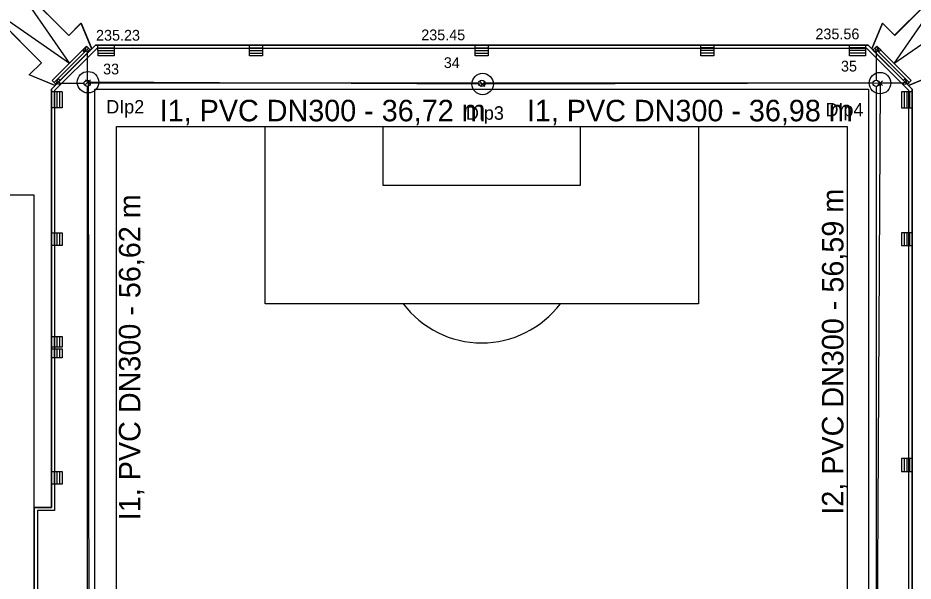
# Model space of a CAD drawing. Extents: x -264234 to -263604, y -1242346 to -1242049.
# Drawn here: x -263895.1 to -263811.8, y -1242154.2 to -1242101.8 of the extents above; entities that cross this region are included whole.
import ezdxf

# ---------------------------------------------------------------- set-up
doc = ezdxf.new("R2010")
doc.units = 0
for name, color, linetype in [('KFA_BODY_CISLO', 7, 'Continuous'), ('KFA_BODY_SYMBOL', 7, 'Continuous'), ('KFA_BODY_VYSKA', 7, 'Continuous'), ('KFA_DAZDOVA_KANALIZACIA_vetva_I', 7, 'Continuous'), ('KFA_DAZDOVA_KANALIZACIA_vetva_I_popis', 7, 'Continuous'), ('KFA_SITUACIA_DSP', 7, 'Continuous')]:
    doc.layers.add(name, color=color, linetype=linetype)

msp = doc.modelspace()

# ---------------------------------------------------------------- linework, layer by layer
at = {"layer": 'KFA_BODY_SYMBOL'}
for p, q in [((-263888.827, -1242107.994), (-263888.385, -1242107.552)), ((-263888.385, -1242107.994), (-263888.827, -1242107.552)), ((-263852.108, -1242108.166), (-263851.666, -1242107.724)), ((-263851.666, -1242108.166), (-263852.108, -1242107.724)), ((-263815.128, -1242108.077), (-263814.686, -1242107.635)), ((-263814.686, -1242108.077), (-263815.128, -1242107.635))]:
    msp.add_line(p, q, dxfattribs=at)
at = {"layer": 'KFA_DAZDOVA_KANALIZACIA_vetva_I'}
for points in [[(-263814.907, -1242107.856), (-263815.198, -1242164.443), (-263815.189, -1242220.791), (-263852.152, -1242220.736), (-263888.701, -1242220.786), (-263906.731, -1242239.259)], [(-263814.907, -1242107.856), (-263851.887, -1242107.945), (-263888.606, -1242107.773), (-263888.523, -1242164.395), (-263888.701, -1242220.786)]]:
    msp.add_lwpolyline(points, dxfattribs=at)
for centre in [(-263888.606, -1242107.773), (-263851.887, -1242107.945), (-263814.907, -1242107.856)]:
    msp.add_circle(centre, 1, dxfattribs=at)
at = {"layer": 'KFA_SITUACIA_DSP'}
for p, q in [((-263891.932, -1242107.613), (-263888.75, -1242104.431)), ((-263891.749, -1242107.795), (-263888.567, -1242104.614)), ((-263888.75, -1242104.431), (-263889.103, -1242104.785)), ((-263888.921, -1242104.967), (-263888.75, -1242104.431)), ((-263888.918, -1242104.964), (-263888.75, -1242104.431)), ((-263888.566, -1242104.615), (-263888.75, -1242104.431)), ((-263888.383, -1242104.797), (-263888.567, -1242104.614)), ((-263887.677, -1242105.332), (-263887.678, -1242104.353)), ((-263887.677, -1242104.582), (-263886.179, -1242104.582)), ((-263886.179, -1242104.332), (-263886.179, -1242105.332)), ((-263873.567, -1242105.332), (-263873.571, -1242104.345)), ((-263873.567, -1242104.582), (-263872.369, -1242104.582)), ((-263872.369, -1242104.332), (-263872.369, -1242105.332)), ((-263852.567, -1242105.332), (-263852.567, -1242104.332)), ((-263852.567, -1242104.582), (-263851.369, -1242104.582)), ((-263851.369, -1242104.332), (-263851.369, -1242105.332)), ((-263831.567, -1242105.332), (-263831.567, -1242104.332)), ((-263830.369, -1242104.582), (-263831.567, -1242104.582)), ((-263830.369, -1242104.332), (-263830.369, -1242105.332)), ((-263817.757, -1242105.332), (-263817.757, -1242104.332)), ((-263816.259, -1242104.582), (-263817.757, -1242104.582)), ((-263816.259, -1242104.332), (-263816.259, -1242105.332)), ((-263815.567, -1242104.787), (-263815.383, -1242104.604)), ((-263815.385, -1242104.605), (-263815.201, -1242104.421)), ((-263812.202, -1242107.786), (-263815.383, -1242104.604)), ((-263812.019, -1242107.603), (-263815.201, -1242104.421)), ((-263815.03, -1242104.957), (-263815.201, -1242104.421)), ((-263815.031, -1242104.959), (-263814.847, -1242104.775)), ((-263888.383, -1242104.797), (-263891.565, -1242107.979)), ((-263888.919, -1242104.969), (-263889.103, -1242104.785)), ((-263889.103, -1242104.785), (-263888.921, -1242104.967)), ((-263888.921, -1242104.967), (-263888.918, -1242104.964)), ((-263888.673, -1242104.962), (-263888.673, -1242107.577)), ((-263887.677, -1242104.832), (-263886.179, -1242104.832)), ((-263887.677, -1242105.082), (-263886.179, -1242105.082)), ((-263886.179, -1242105.332), (-263887.677, -1242105.332)), ((-263873.567, -1242104.832), (-263872.369, -1242104.832)), ((-263873.567, -1242105.082), (-263872.369, -1242105.082)), ((-263872.369, -1242105.332), (-263873.567, -1242105.332)), ((-263852.567, -1242104.832), (-263851.369, -1242104.832)), ((-263852.567, -1242105.082), (-263851.369, -1242105.082)), ((-263851.369, -1242105.332), (-263852.567, -1242105.332)), ((-263830.369, -1242104.832), (-263831.567, -1242104.832)), ((-263830.369, -1242105.082), (-263831.567, -1242105.082)), ((-263830.369, -1242105.332), (-263831.567, -1242105.332)), ((-263816.259, -1242104.832), (-263817.757, -1242104.832)), ((-263816.259, -1242105.082), (-263817.757, -1242105.082)), ((-263816.259, -1242105.332), (-263817.757, -1242105.332)), ((-263815.567, -1242104.787), (-263812.385, -1242107.97)), ((-263815.263, -1242104.962), (-263815.263, -1242107.577)), ((-263891.748, -1242107.797), (-263891.932, -1242107.613)), ((-263891.396, -1242107.442), (-263891.749, -1242107.795)), ((-263891.565, -1242107.979), (-263891.749, -1242107.795)), ((-263891.749, -1242107.795), (-263891.565, -1242107.979)), ((-263891.517, -1242107.934), (-263891.673, -1242108.089)), ((-263891.565, -1242107.979), (-263891.396, -1242107.442)), ((-263891.565, -1242107.979), (-263891.396, -1242107.442)), ((-263891.212, -1242107.626), (-263891.396, -1242107.442)), ((-263891.218, -1242107.877), (-263888.973, -1242107.877)), ((-263852.268, -1242107.877), (-263888.373, -1242107.877)), ((-263815.563, -1242107.877), (-263851.668, -1242107.877)), ((-263812.717, -1242107.877), (-263814.963, -1242107.877)), ((-263812.739, -1242107.616), (-263812.555, -1242107.432)), ((-263812.385, -1242107.97), (-263812.555, -1242107.432)), ((-263812.385, -1242107.97), (-263812.202, -1242107.786)), ((-263812.203, -1242107.787), (-263812.019, -1242107.603)), ((-263891.018, -1242108.673), (-263892.012, -1242108.664)), ((-263891.768, -1242108.673), (-263891.768, -1242110.171)), ((-263891.518, -1242108.673), (-263891.518, -1242110.171)), ((-263891.268, -1242108.673), (-263891.268, -1242110.171)), ((-263891.018, -1242108.673), (-263891.018, -1242110.171)), ((-263888.673, -1242108.177), (-263888.673, -1242164.087)), ((-263815.263, -1242108.177), (-263815.263, -1242164.087)), ((-263811.918, -1242108.673), (-263812.918, -1242108.673)), ((-263812.918, -1242108.673), (-263812.918, -1242110.172)), ((-263812.668, -1242108.673), (-263812.668, -1242110.172)), ((-263812.418, -1242108.673), (-263812.418, -1242110.172)), ((-263812.168, -1242108.673), (-263812.168, -1242110.172)), ((-263891.018, -1242110.171), (-263891.997, -1242110.171)), ((-263812.918, -1242110.172), (-263811.918, -1242110.172)), ((-263892.018, -1242121.782), (-263891.018, -1242121.782)), ((-263891.768, -1242121.782), (-263891.768, -1242122.982)), ((-263891.518, -1242121.782), (-263891.518, -1242122.982)), ((-263891.268, -1242121.782), (-263891.268, -1242122.982)), ((-263891.018, -1242121.782), (-263891.018, -1242122.982)), ((-263811.918, -1242121.782), (-263812.918, -1242121.782)), ((-263812.918, -1242121.782), (-263812.918, -1242122.982)), ((-263812.668, -1242121.782), (-263812.668, -1242122.982)), ((-263812.418, -1242121.782), (-263812.418, -1242122.982)), ((-263812.168, -1242121.782), (-263812.168, -1242122.982)), ((-263891.018, -1242122.982), (-263892.018, -1242122.982)), ((-263812.918, -1242122.982), (-263811.918, -1242122.982)), ((-263891.997, -1242131.433), (-263891.018, -1242131.433)), ((-263891.768, -1242131.433), (-263891.768, -1242132.431)), ((-263891.518, -1242131.433), (-263891.518, -1242132.431)), ((-263891.268, -1242131.433), (-263891.268, -1242132.431)), ((-263891.018, -1242131.433), (-263891.018, -1242132.431)), ((-263891.018, -1242132.431), (-263892.018, -1242132.431)), ((-263892.018, -1242132.583), (-263891.018, -1242132.583)), ((-263891.768, -1242132.583), (-263891.768, -1242133.431)), ((-263891.518, -1242132.583), (-263891.518, -1242133.431)), ((-263891.268, -1242132.583), (-263891.268, -1242133.431)), ((-263891.018, -1242132.583), (-263891.018, -1242133.431)), ((-263891.018, -1242133.431), (-263892.018, -1242133.431)), ((-263811.918, -1242142.782), (-263812.918, -1242142.782)), ((-263812.918, -1242142.782), (-263812.918, -1242143.982)), ((-263812.668, -1242142.782), (-263812.668, -1242143.982)), ((-263812.418, -1242142.782), (-263812.418, -1242143.982)), ((-263812.168, -1242142.782), (-263812.168, -1242143.982)), ((-263892.018, -1242143.983), (-263891.018, -1242143.983)), ((-263891.768, -1242143.983), (-263891.768, -1242145.181)), ((-263891.518, -1242143.983), (-263891.518, -1242145.181)), ((-263891.268, -1242143.983), (-263891.268, -1242145.181)), ((-263891.018, -1242143.983), (-263891.018, -1242145.181)), ((-263812.918, -1242143.982), (-263811.918, -1242143.982)), ((-263891.018, -1242145.181), (-263892.018, -1242145.181))]:
    msp.add_line(p, q, dxfattribs=at)
for points in [[(-263891.681, -1242108.095), (-263894.08, -1242107.101), (-263892.944, -1242105.964), (-263898.552, -1242100.364), (-263896.003, -1242097.814), (-263890.399, -1242103.418), (-263889.262, -1242102.282), (-263888.268, -1242104.681), (-263891.681, -1242108.095)], [(-263898.54, -1242100.355), (-263895.995, -1242097.81), (-263890.341, -1242106.025), (-263898.533, -1242100.366)], [(-263812.269, -1242108.085), (-263809.87, -1242107.09), (-263811.006, -1242105.954), (-263805.4, -1242100.352), (-263807.949, -1242097.803), (-263813.552, -1242103.408), (-263814.689, -1242102.272), (-263815.683, -1242104.672), (-263812.269, -1242108.085)], [(-263805.395, -1242100.355), (-263807.941, -1242097.809), (-263813.618, -1242106.02), (-263805.402, -1242100.365)], [(-263893.618, -1242181.432), (-263893.618, -1242147.332), (-263892.018, -1242147.332), (-263892.018, -1242108.434), (-263891.673, -1242108.09), (-263894.073, -1242107.096), (-263892.937, -1242105.959), (-263896.896, -1242101.999), (-263894.351, -1242099.454), (-263890.391, -1242103.413), (-263889.254, -1242102.277), (-263888.26, -1242104.677), (-263887.916, -1242104.332), (-263816.02, -1242104.332), (-263815.675, -1242104.677), (-263814.681, -1242102.277), (-263813.545, -1242103.413), (-263809.585, -1242099.454), (-263807.039, -1242101.999), (-263810.999, -1242105.959), (-263809.862, -1242107.096), (-263812.262, -1242108.09), (-263811.918, -1242108.434), (-263811.918, -1242220.33)]]:
    msp.add_lwpolyline(points, dxfattribs=at)
for points in [[(-263816.02, -1242224.432), (-263811.918, -1242220.33), (-263811.918, -1242108.434), (-263816.02, -1242104.332), (-263887.916, -1242104.332), (-263892.018, -1242108.434), (-263892.018, -1242147.332), (-263893.618, -1242147.332), (-263893.618, -1242162.382), (-263894.718, -1242162.382), (-263894.718, -1242166.382), (-263893.618, -1242166.382), (-263893.618, -1242181.432), (-263892.018, -1242181.432), (-263892.018, -1242220.33), (-263887.916, -1242224.432)], [(-263816.144, -1242224.132), (-263812.218, -1242220.206), (-263812.218, -1242108.558), (-263816.144, -1242104.632), (-263887.792, -1242104.632), (-263891.718, -1242108.558), (-263891.718, -1242147.632), (-263893.318, -1242147.632), (-263893.318, -1242162.682), (-263894.418, -1242162.682), (-263894.418, -1242166.082), (-263893.318, -1242166.082), (-263893.318, -1242181.132), (-263891.718, -1242181.132), (-263891.718, -1242220.206), (-263887.792, -1242224.132)], [(-263815.201, -1242104.421), (-263815.03, -1242104.957), (-263814.847, -1242104.775)], [(-263812.385, -1242107.97), (-263812.202, -1242107.786), (-263812.555, -1242107.432)], [(-263887.968, -1242108.434), (-263815.968, -1242108.434), (-263815.968, -1242220.33), (-263887.968, -1242220.33)], [(-263885.968, -1242111.882), (-263817.968, -1242111.882), (-263817.968, -1242216.882), (-263885.968, -1242216.882)], [(-263831.808, -1242128.382), (-263872.128, -1242128.382), (-263872.128, -1242111.882), (-263831.808, -1242111.882)], [(-263842.808, -1242117.382), (-263861.128, -1242117.382), (-263861.128, -1242111.882), (-263842.808, -1242111.882)], [(-263893.618, -1242118.282), (-263916.093, -1242118.282), (-263916.093, -1242175.482), (-263914.293, -1242175.482), (-263914.293, -1242210.482), (-263893.618, -1242210.482), (-263893.618, -1242166.382), (-263900.043, -1242166.382), (-263900.043, -1242162.382), (-263893.618, -1242162.382)]]:
    msp.add_lwpolyline(points, close=True, dxfattribs=at)
for centre, radius in [((-263888.673, -1242104.862), 0.1), ((-263815.263, -1242104.862), 0.1), ((-263891.318, -1242107.877), 0.1), ((-263888.673, -1242107.877), 0.3), ((-263851.968, -1242107.877), 0.3), ((-263815.263, -1242107.877), 0.3), ((-263812.617, -1242107.877), 0.1)]:
    msp.add_circle(centre, radius, dxfattribs=at)
msp.add_arc((-263851.968, -1242122.882), 9.15, 216.94821, 323.05179, dxfattribs=at)

# ---------------------------------------------------------------- texts
at = {"layer": 'KFA_BODY_CISLO'}
for s, p in [('34', (-263855.497, -1242106.454)), ('33', (-263887.203, -1242107.046)), ('35', (-263818.541, -1242106.781))]:
    msp.add_text(s, height=1, dxfattribs=at).set_placement(p)
at = {"layer": 'KFA_BODY_VYSKA'}
for s, p in [('235.23', (-263887.86, -1242103.906)), ('235.45', (-263857.599, -1242103.87)), ('235.56', (-263820.918, -1242103.781))]:
    msp.add_text(s, height=1, dxfattribs=at).set_placement(p)
at = {"layer": 'KFA_DAZDOVA_KANALIZACIA_vetva_I_popis'}
for s, height, p in [('DIp2', 1.25, (-263886.906, -1242110.683)), ('I1, PVC DN300 - 36,72 m', 2, (-263881.934, -1242111.412)), ('I1, PVC DN300 - 36,98 m', 2, (-263847.77, -1242111.412)), ('DIp4', 1.25, (-263819.984, -1242110.954)), ('DIp3', 1.25, (-263853.442, -1242111.265))]:
    msp.add_text(s, height=height, dxfattribs=at).set_placement(p)
for s, p in [('I2, PVC DN300 - 56,59 m', (-263818.311, -1242148.012)), ('I1, PVC DN300 - 56,62 m', (-263883.733, -1242148.526))]:
    msp.add_text(s, height=2, rotation=90, dxfattribs=at).set_placement(p)

doc.saveas('drawing.dxf')
